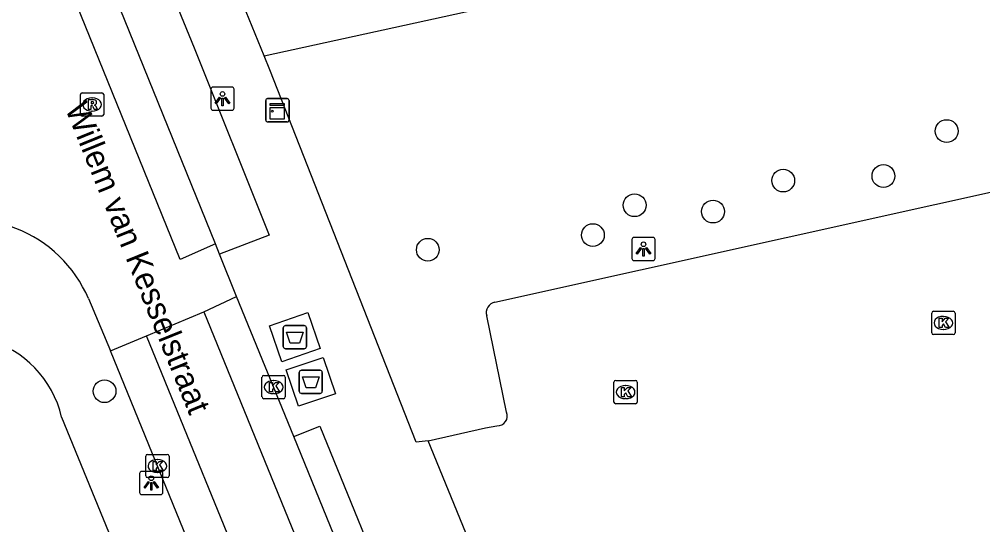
# Model space of a CAD drawing. Extents: x 160037 to 160839, y 385326 to 386441.
# Drawn here: x 160686.15 to 160727.52, y 385612.41 to 385634.11 of the extents above; entities that cross this region are included whole.
import ezdxf

# ---------------------------------------------------------------- set-up
doc = ezdxf.new("R2010")
doc.units = 0
for name, color, linetype in [('IMGEO_Afval_apart_plaats', 7, 'Continuous'), ('IMGEO_Boom', 7, 'Continuous'), ('IMGEO_Kast', 7, 'Continuous'), ('IMGEO_Kolk', 7, 'Continuous'), ('IMGEO_Lichtpunt', 7, 'Continuous'), ('IMGEO_Openbare_ruimte_label', 7, 'Continuous'), ('IMGEO_Parkeervlak_open', 7, 'Continuous'), ('IMGEO_Rijbaan_lokaal_gesloten', 7, 'Continuous'), ('IMGEO_Rijbaan_lokaal_open', 7, 'Continuous'), ('IMGEO_Rioolput', 7, 'Continuous'), ('IMGEO_Voetpad_gesloten', 7, 'Continuous'), ('IMGEO_Voetpad_open', 7, 'Continuous')]:
    doc.layers.add(name, color=color, linetype=linetype)

msp = doc.modelspace()

# ---------------------------------------------------------------- linework, layer by layer
at = {"layer": 'IMGEO_Afval_apart_plaats'}
for p, q in [((160697.585, 385620.964), (160698.375, 385620.964)), ((160698.375, 385620.964), (160697.585, 385620.964)), ((160697.485, 385620.064), (160697.485, 385620.864)), ((160697.485, 385620.864), (160697.485, 385620.064)), ((160698.475, 385620.864), (160698.475, 385620.064)), ((160698.475, 385620.064), (160698.475, 385620.864)), ((160698.375, 385619.964), (160697.585, 385619.964)), ((160697.585, 385619.964), (160698.375, 385619.964)), ((160698.17, 385618.147), (160698.17, 385618.947)), ((160698.17, 385618.947), (160698.17, 385618.147)), ((160698.27, 385619.047), (160699.06, 385619.047)), ((160699.06, 385619.047), (160698.27, 385619.047)), ((160699.16, 385618.947), (160699.16, 385618.147)), ((160699.16, 385618.147), (160699.16, 385618.947)), ((160699.06, 385618.047), (160698.27, 385618.047)), ((160698.27, 385618.047), (160699.06, 385618.047))]:
    msp.add_line(p, q, dxfattribs=at)
for points in [[(160697.628, 385620.678), (160698.332, 385620.678), (160698.183, 385620.208), (160697.777, 385620.208), (160697.628, 385620.678)], [(160698.313, 385618.761), (160699.017, 385618.761), (160698.868, 385618.291), (160698.462, 385618.291), (160698.313, 385618.761)]]:
    msp.add_lwpolyline(points, dxfattribs=at)
for centre, start, end in [((160697.585, 385620.864), 90, 180), ((160697.585, 385620.864), 90, 180), ((160698.375, 385620.864), 0, 90), ((160698.375, 385620.864), 360, 90), ((160697.585, 385620.064), 180, 270), ((160697.585, 385620.064), 180, 270), ((160698.375, 385620.064), 270, 0), ((160698.375, 385620.064), 270, 0), ((160698.27, 385618.947), 90, 180), ((160698.27, 385618.947), 90, 180), ((160699.06, 385618.947), 0, 90), ((160699.06, 385618.947), 360, 90), ((160698.27, 385618.147), 180, 270), ((160698.27, 385618.147), 180, 270), ((160699.06, 385618.147), 270, 0), ((160699.06, 385618.147), 270, 0)]:
    msp.add_arc(centre, 0.1, start, end, dxfattribs=at)
at = {"layer": 'IMGEO_Boom'}
for centre in [(160725.969, 385629.314), (160718.951, 385627.188), (160723.253, 385627.382), (160712.57, 385626.128), (160715.937, 385625.856), (160710.777, 385624.847), (160703.69, 385624.217), (160689.807, 385618.144)]:
    msp.add_circle(centre, 0.489, dxfattribs=at)
at = {"layer": 'IMGEO_Kast'}
for p, q in [((160696.732, 385629.78), (160696.732, 385630.621)), ((160696.732, 385630.621), (160696.732, 385629.78)), ((160696.807, 385630.705), (160697.648, 385630.705)), ((160697.648, 385630.705), (160696.807, 385630.705)), ((160697.732, 385630.63), (160697.732, 385629.789)), ((160697.732, 385629.789), (160697.732, 385630.63)), ((160697.657, 385629.705), (160696.816, 385629.705)), ((160696.816, 385629.705), (160697.657, 385629.705))]:
    msp.add_line(p, q, dxfattribs=at)
for points in [[(160696.927, 385630.495), (160697.527, 385630.495), (160697.527, 385630.41), (160696.927, 385630.41), (160696.927, 385630.495)], [(160696.927, 385630.32), (160697.527, 385630.32), (160697.527, 385629.831), (160696.927, 385629.831), (160696.927, 385630.32)]]:
    msp.add_lwpolyline(points, dxfattribs=at)
msp.add_circle((160697.011, 385630.169), 0.0377, dxfattribs=at)
for centre, start, end in [((160696.81, 385630.627), 92.4484, 184.2845), ((160696.81, 385630.627), 92.4484, 184.2845), ((160697.654, 385630.627), 2.4484, 94.2845), ((160697.654, 385630.627), 2.4484, 94.2845), ((160696.81, 385629.783), 182.4484, 274.2845), ((160696.81, 385629.783), 182.4484, 274.2845), ((160697.654, 385629.783), 272.4484, 4.2845), ((160697.654, 385629.783), 272.4484, 4.2845)]:
    msp.add_arc(centre, 0.0779, start, end, dxfattribs=at)
at = {"layer": 'IMGEO_Kolk'}
for p, q in [((160725.328, 385620.648), (160725.328, 385621.5)), ((160725.403, 385621.574), (160726.255, 385621.574)), ((160726.329, 385621.5), (160726.329, 385620.648)), ((160725.816, 385621.354), (160725.841, 385621.354)), ((160726.255, 385620.574), (160725.403, 385620.574)), ((160725.839, 385620.794), (160725.814, 385620.794)), ((160696.569, 385617.895), (160696.569, 385618.747)), ((160696.644, 385618.821), (160697.496, 385618.821)), ((160697.057, 385618.601), (160697.082, 385618.601)), ((160697.57, 385618.747), (160697.57, 385617.895)), ((160711.684, 385617.679), (160711.684, 385618.531)), ((160711.759, 385618.605), (160712.611, 385618.605)), ((160712.685, 385618.531), (160712.685, 385617.679)), ((160712.172, 385618.385), (160712.197, 385618.385)), ((160697.496, 385617.821), (160696.644, 385617.821)), ((160697.08, 385618.041), (160697.055, 385618.041)), ((160712.195, 385617.825), (160712.17, 385617.825)), ((160712.611, 385617.605), (160711.759, 385617.605)), ((160691.575, 385614.506), (160691.575, 385615.358)), ((160691.65, 385615.432), (160692.502, 385615.432)), ((160692.063, 385615.212), (160692.088, 385615.212)), ((160692.576, 385615.358), (160692.576, 385614.506)), ((160692.502, 385614.432), (160691.65, 385614.432)), ((160692.086, 385614.652), (160692.061, 385614.652))]:
    msp.add_line(p, q, dxfattribs=at)
for points in [[(160725.328, 385620.648), (160725.328, 385621.5)], [(160725.403, 385621.574), (160726.255, 385621.574)], [(160726.329, 385621.5), (160726.329, 385620.648)], [(160725.649, 385621.274), (160725.772, 385621.274), (160725.772, 385621.123), (160725.902, 385621.274), (160726.066, 385621.274), (160725.92, 385621.123), (160726.073, 385620.874), (160725.921, 385620.874), (160725.836, 385621.038), (160725.772, 385620.971), (160725.772, 385620.874), (160725.649, 385620.874), (160725.649, 385621.274)], [(160726.255, 385620.574), (160725.403, 385620.574)], [(160696.569, 385617.895), (160696.569, 385618.747)], [(160696.644, 385618.821), (160697.496, 385618.821)], [(160696.89, 385618.521), (160697.013, 385618.521), (160697.013, 385618.37), (160697.143, 385618.521), (160697.307, 385618.521), (160697.161, 385618.37), (160697.314, 385618.121), (160697.162, 385618.121), (160697.077, 385618.285), (160697.013, 385618.218), (160697.013, 385618.121), (160696.89, 385618.121), (160696.89, 385618.521)], [(160697.57, 385618.747), (160697.57, 385617.895)], [(160711.684, 385617.679), (160711.684, 385618.531)], [(160711.759, 385618.605), (160712.611, 385618.605)], [(160712.685, 385618.531), (160712.685, 385617.679)], [(160712.005, 385618.305), (160712.128, 385618.305), (160712.128, 385618.154), (160712.258, 385618.305), (160712.422, 385618.305), (160712.276, 385618.154), (160712.429, 385617.905), (160712.277, 385617.905), (160712.192, 385618.069), (160712.128, 385618.002), (160712.128, 385617.905), (160712.005, 385617.905), (160712.005, 385618.305)], [(160697.496, 385617.821), (160696.644, 385617.821)], [(160712.611, 385617.605), (160711.759, 385617.605)], [(160691.575, 385614.506), (160691.575, 385615.358)], [(160691.65, 385615.432), (160692.502, 385615.432)], [(160692.576, 385615.358), (160692.576, 385614.506)], [(160691.896, 385615.132), (160692.019, 385615.132), (160692.019, 385614.981), (160692.149, 385615.132), (160692.313, 385615.132), (160692.167, 385614.981), (160692.32, 385614.732), (160692.168, 385614.732), (160692.083, 385614.896), (160692.019, 385614.829), (160692.019, 385614.732), (160691.896, 385614.732), (160691.896, 385615.132)], [(160692.502, 385614.432), (160691.65, 385614.432)]]:
    msp.add_lwpolyline(points, dxfattribs=at)
for centre, start, end in [((160725.405, 385621.498), 91.552, 178.448), ((160725.405, 385621.498), 91.552, 178.448), ((160726.253, 385621.498), 1.552, 88.448), ((160726.253, 385621.498), 1.552, 88.448), ((160725.405, 385620.65), 181.552, 268.448), ((160725.405, 385620.65), 181.552, 268.448), ((160726.253, 385620.65), 271.552, 358.448), ((160726.253, 385620.65), 271.552, 358.448), ((160696.646, 385618.745), 91.552, 178.448), ((160696.646, 385618.745), 91.552, 178.448), ((160697.494, 385618.745), 1.552, 88.448), ((160697.494, 385618.745), 1.552, 88.448), ((160711.761, 385618.529), 91.552, 178.448), ((160711.761, 385618.529), 91.552, 178.448), ((160712.609, 385618.529), 1.552, 88.448), ((160712.609, 385618.529), 1.552, 88.448), ((160696.646, 385617.897), 181.552, 268.448), ((160696.646, 385617.897), 181.552, 268.448), ((160697.494, 385617.897), 271.552, 358.448), ((160697.494, 385617.897), 271.552, 358.448), ((160711.761, 385617.681), 181.552, 268.448), ((160711.761, 385617.681), 181.552, 268.448), ((160712.609, 385617.681), 271.552, 358.448), ((160712.609, 385617.681), 271.552, 358.448), ((160691.652, 385615.356), 91.552, 178.448), ((160691.652, 385615.356), 91.552, 178.448), ((160692.5, 385615.356), 1.552, 88.448), ((160692.5, 385615.356), 1.552, 88.448), ((160691.652, 385614.508), 181.552, 268.448), ((160691.652, 385614.508), 181.552, 268.448), ((160692.5, 385614.508), 271.552, 358.448), ((160692.5, 385614.508), 271.552, 358.448)]:
    msp.add_arc(centre, 0.0765, start, end, dxfattribs=at)
for centre, major_axis, ratio, start_param, end_param in [((160725.815, 385621.074), (-0.387, 0.002), 0.722429, 4.712389, 7.853982), ((160725.84, 385621.074), (-0.39, 0.002), 0.717154, 1.570796, 4.712389), ((160697.056, 385618.321), (-0.387, 0.002), 0.722429, 4.712389, 7.853982), ((160697.081, 385618.321), (-0.39, 0.002), 0.717154, 1.570796, 4.712389), ((160712.171, 385618.105), (-0.387, 0.002), 0.722429, 4.712389, 7.853982), ((160712.196, 385618.105), (-0.39, 0.002), 0.717154, 1.570796, 4.712389), ((160692.062, 385614.932), (-0.387, 0.002), 0.722429, 4.712389, 7.853982), ((160692.087, 385614.932), (-0.39, 0.002), 0.717154, 1.570796, 4.712389)]:
    msp.add_ellipse(centre, major_axis=major_axis, ratio=ratio, start_param=start_param, end_param=end_param, dxfattribs=at)
at = {"layer": 'IMGEO_Lichtpunt'}
for p, q in [((160694.374, 385631.108), (160694.374, 385630.301)), ((160694.374, 385631.108), (160694.374, 385630.301)), ((160695.276, 385631.203), (160694.468, 385631.203)), ((160695.276, 385631.203), (160694.468, 385631.203)), ((160695.37, 385630.301), (160695.37, 385631.108)), ((160695.37, 385630.301), (160695.37, 385631.108)), ((160694.468, 385630.207), (160695.276, 385630.207)), ((160694.468, 385630.207), (160695.276, 385630.207)), ((160713.354, 385624.75), (160712.546, 385624.75)), ((160713.354, 385624.75), (160712.546, 385624.75)), ((160712.452, 385624.655), (160712.452, 385623.848)), ((160712.452, 385624.655), (160712.452, 385623.848)), ((160713.448, 385623.848), (160713.448, 385624.655)), ((160713.448, 385623.848), (160713.448, 385624.655)), ((160712.546, 385623.754), (160713.354, 385623.754)), ((160712.546, 385623.754), (160713.354, 385623.754)), ((160691.316, 385614.607), (160691.316, 385613.8)), ((160691.316, 385614.607), (160691.316, 385613.8)), ((160692.218, 385614.702), (160691.41, 385614.702)), ((160692.218, 385614.702), (160691.41, 385614.702)), ((160692.312, 385613.8), (160692.312, 385614.607)), ((160692.312, 385613.8), (160692.312, 385614.607)), ((160691.41, 385613.706), (160692.218, 385613.706)), ((160691.41, 385613.706), (160692.218, 385613.706))]:
    msp.add_line(p, q, dxfattribs=at)
for points in [[(160694.748, 385630.772), (160694.787, 385630.744), (160694.599, 385630.482), (160694.561, 385630.509), (160694.748, 385630.772)], [(160694.85, 385630.724), (160694.897, 385630.724), (160694.897, 385630.402), (160694.85, 385630.402), (160694.85, 385630.724)], [(160694.96, 385630.744), (160694.998, 385630.771), (160695.185, 385630.509), (160695.146, 385630.481), (160694.96, 385630.744)], [(160712.826, 385624.319), (160712.865, 385624.291), (160712.677, 385624.029), (160712.639, 385624.056), (160712.826, 385624.319)], [(160712.928, 385624.271), (160712.975, 385624.271), (160712.975, 385623.949), (160712.928, 385623.949), (160712.928, 385624.271)], [(160713.038, 385624.291), (160713.076, 385624.318), (160713.263, 385624.056), (160713.224, 385624.028), (160713.038, 385624.291)], [(160691.69, 385614.271), (160691.729, 385614.243), (160691.541, 385613.981), (160691.503, 385614.008), (160691.69, 385614.271)], [(160691.792, 385614.223), (160691.839, 385614.223), (160691.839, 385613.901), (160691.792, 385613.901), (160691.792, 385614.223)], [(160691.902, 385614.243), (160691.94, 385614.27), (160692.127, 385614.008), (160692.088, 385613.98), (160691.902, 385614.243)]]:
    msp.add_lwpolyline(points, dxfattribs=at)
for centre in [(160694.873, 385630.906), (160712.951, 385624.453), (160691.815, 385614.405)]:
    msp.add_circle(centre, 0.0994, dxfattribs=at)
for centre, start, end in [((160694.468, 385631.108), 90, 180), ((160694.468, 385631.108), 90, 180), ((160695.276, 385631.108), 0, 90), ((160695.276, 385631.108), 0, 90), ((160694.468, 385630.301), 180, 270), ((160694.468, 385630.301), 180, 270), ((160695.276, 385630.301), 270, 0), ((160695.276, 385630.301), 270, 360), ((160712.546, 385624.655), 90, 180), ((160712.546, 385624.655), 90, 180), ((160713.354, 385624.655), 0, 90), ((160713.354, 385624.655), 0, 90), ((160712.546, 385623.848), 180, 270), ((160712.546, 385623.848), 180, 270), ((160713.354, 385623.848), 270, 0), ((160713.354, 385623.848), 270, 360), ((160691.41, 385614.607), 90, 180), ((160691.41, 385614.607), 90, 180), ((160692.218, 385614.607), 0, 90), ((160692.218, 385614.607), 0, 90), ((160691.41, 385613.8), 180, 270), ((160691.41, 385613.8), 180, 270), ((160692.218, 385613.8), 270, 0), ((160692.218, 385613.8), 270, 360)]:
    msp.add_arc(centre, 0.0946, start, end, dxfattribs=at)
at = {"layer": 'IMGEO_Parkeervlak_open'}
for points in [[(160706.573, 385621.963), (160737.965, 385628.931), (160740.966, 385629.273), (160759.505, 385633.343)], [(160707.074, 385617.242), (160706.217, 385621.378)], [(160703.709, 385616.016), (160706.16, 385616.577), (160706.66, 385616.657)]]:
    msp.add_lwpolyline(points, dxfattribs=at)
for centre, radius, start, end in [((160706.653, 385621.514), 0.456, 100.0751, 197.28), ((160706.677, 385617.084), 0.427, 267.6604, 21.7661)]:
    msp.add_arc(centre, radius, start, end, dxfattribs=at)
at = {"layer": 'IMGEO_Rijbaan_lokaal_gesloten'}
for points in [[(160694.574, 385624.472), (160688.016, 385640.644)], [(160697.943, 385616.194), (160695.475, 385622.21)], [(160694.076, 385621.556), (160703.188, 385599.205), (160706.065, 385591.61)], [(160701.48, 385596.364), (160691.604, 385620.527)], [(160699.908, 385595.734), (160690.059, 385619.877)], [(160701.37, 385607.768), (160697.943, 385616.194)]]:
    msp.add_lwpolyline(points, dxfattribs=at)
at = {"layer": 'IMGEO_Rijbaan_lokaal_open'}
for points in [[(160694.574, 385624.472), (160693.055, 385623.795), (160686.465, 385640.026), (160688.016, 385640.644)], [(160694.745, 385624.022), (160694.574, 385624.472)], [(160695.475, 385622.21), (160694.745, 385624.022)], [(160694.076, 385621.556), (160695.475, 385622.21)], [(160689.115, 385622.125), (160690.059, 385619.877)], [(160691.604, 385620.527), (160694.076, 385621.556)], [(160690.059, 385619.877), (160691.604, 385620.527)]]:
    msp.add_lwpolyline(points, dxfattribs=at)
msp.add_arc((160683.957, 385619.908), 5.614, 23.2588, 114.0487, dxfattribs=at)
at = {"layer": 'IMGEO_Rioolput'}
for p, q in [((160688.771, 385630.028), (160688.771, 385630.88)), ((160688.846, 385630.954), (160689.698, 385630.954)), ((160689.772, 385630.88), (160689.772, 385630.028)), ((160689.259, 385630.734), (160689.284, 385630.734)), ((160689.282, 385630.174), (160689.257, 385630.174)), ((160689.698, 385629.954), (160688.846, 385629.954))]:
    msp.add_line(p, q, dxfattribs=at)
for points in [[(160688.771, 385630.028), (160688.771, 385630.88)], [(160688.846, 385630.954), (160689.698, 385630.954)], [(160689.772, 385630.88), (160689.772, 385630.028)], [(160689.36, 385630.652), (160689.108, 385630.654), (160689.108, 385630.254)], [(160689.286, 385630.573), (160689.232, 385630.573), (160689.232, 385630.492)], [(160689.232, 385630.492), (160689.284, 385630.492)], [(160689.108, 385630.254), (160689.232, 385630.254), (160689.232, 385630.416), (160689.243, 385630.416)], [(160689.29, 385630.387), (160689.361, 385630.254), (160689.501, 385630.254), (160689.436, 385630.38)], [(160689.698, 385629.954), (160688.846, 385629.954)]]:
    msp.add_lwpolyline(points, dxfattribs=at)
for centre, radius, start, end in [((160688.848, 385630.878), 0.0765, 91.552, 178.448), ((160688.848, 385630.878), 0.0765, 91.552, 178.448), ((160689.696, 385630.878), 0.0765, 1.552, 88.448), ((160689.696, 385630.878), 0.0765, 1.552, 88.448), ((160689.268, 385630.681), 0.19, 274.7715, 282.9687), ((160689.292, 385630.477), 0.0964, 77.0061, 93.1865), ((160689.306, 385630.534), 0.0378, 276.6634, 79.6772), ((160689.359, 385630.542), 0.109, 350.3612, 89.416), ((160689.357, 385630.542), 0.112, 277.5842, 350.9817), ((160689.242, 385630.363), 0.0533, 26.0293, 88.6989), ((160689.341, 385630.327), 0.108, 29.5134, 73.7905), ((160688.848, 385630.03), 0.0765, 181.552, 268.448), ((160688.848, 385630.03), 0.0765, 181.552, 268.448), ((160689.696, 385630.03), 0.0765, 271.552, 358.448), ((160689.696, 385630.03), 0.0765, 271.552, 358.448)]:
    msp.add_arc(centre, radius, start, end, dxfattribs=at)
for centre, major_axis, ratio, start_param, end_param in [((160689.258, 385630.454), (-0.387, 0.002), 0.722429, 4.712389, 7.853982), ((160689.283, 385630.454), (-0.39, 0.002), 0.717154, 1.570796, 4.712389)]:
    msp.add_ellipse(centre, major_axis=major_axis, ratio=ratio, start_param=start_param, end_param=end_param, dxfattribs=at)
at = {"layer": 'IMGEO_Voetpad_gesloten'}
for points in [[(160697.424, 385619.409), (160696.891, 385620.949), (160698.535, 385621.519), (160699.068, 385619.978), (160697.424, 385619.409)], [(160698.137, 385617.499), (160697.61, 385619.061), (160699.193, 385619.595), (160699.72, 385618.033), (160698.137, 385617.499)]]:
    msp.add_lwpolyline(points, dxfattribs=at)
at = {"layer": 'IMGEO_Voetpad_open'}
for points in [[(160696.668, 385632.545), (160727.249, 385639.24), (160753.839, 385645.047), (160758.778, 385646.124)], [(160687.977, 385640.739), (160690.097, 385641.586), (160693.652, 385632.886), (160696.878, 385624.838), (160694.745, 385624.022)], [(160696.668, 385632.545), (160695.894, 385634.44)], [(160703.709, 385616.016), (160703.192, 385615.95), (160696.905, 385631.943), (160696.668, 385632.545)], [(160687.965, 385617.033), (160695.737, 385598.058)], [(160697.943, 385616.194), (160699.059, 385616.636), (160702.472, 385608.262), (160701.37, 385607.768)], [(160707.926, 385610.625), (160706.197, 385609.931), (160703.709, 385616.016)]]:
    msp.add_lwpolyline(points, dxfattribs=at)
msp.add_arc((160683.558, 385616.004), 4.525, 13.1416, 74.7427, dxfattribs=at)

# ---------------------------------------------------------------- texts
at = {"layer": 'IMGEO_Openbare_ruimte_label'}
msp.add_text('Willem van Kesselstraat', height=1, rotation=292.0779, dxfattribs=at).set_placement((160688.099, 385630.296))

doc.saveas('drawing.dxf')
